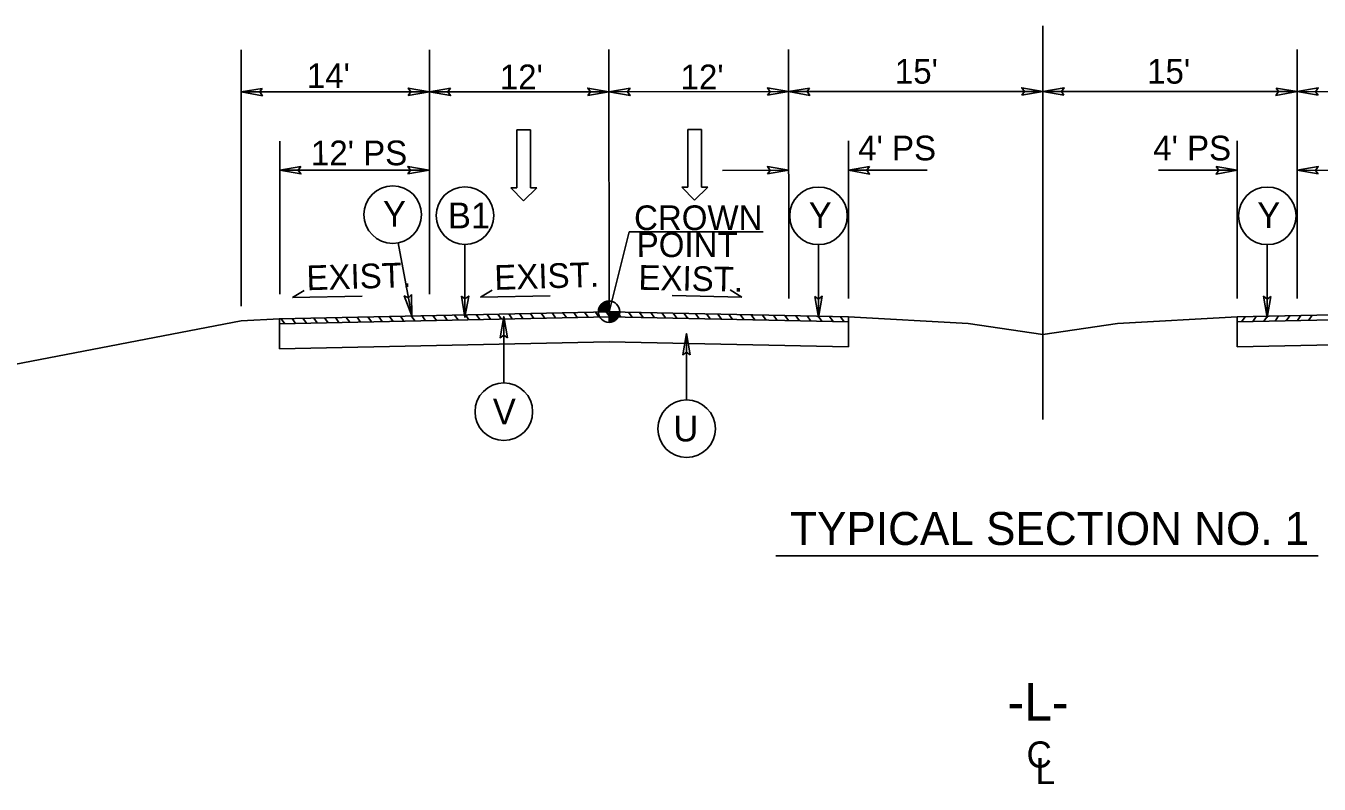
# Model space of a CAD drawing. Extents: x 2241081 to 2251104, y 658534 to 663427.
# Drawn here: x 2248203.4 to 2248635.4, y 662128.3 to 662381.6 of the extents above; entities that cross this region are included whole.
import ezdxf

# ---------------------------------------------------------------- set-up
doc = ezdxf.new("R2010")
doc.units = 0
for name, color, linetype in [('Old_Level_2', 7, 'Continuous'), ('Prop Dimension Text', 7, 'Continuous'), ('Prop Lane Arrow CELL', 7, 'Continuous'), ('Prop Shade Medium', 7, 'Continuous'), ('Prop Terminator CELL', 7, 'Continuous'), ('Typical Arrow Superelevation CELL', 7, 'Continuous'), ('Typical Berm Information CELL', 7, 'Continuous'), ('Typical Grade Point Symbol CELL', 7, 'Continuous'), ('Typical ID Circle CELL', 7, 'Continuous'), ('Typical Terminator CELL', 7, 'Continuous'), ('Typical Text Centerline CELL', 7, 'Continuous'), ('Typical Text Grade Point CELL', 7, 'Continuous'), ('Typical Text ID Circle CELL', 7, 'Continuous'), ('Typical Text Label CELL', 7, 'Continuous')]:
    doc.layers.add(name, color=color, linetype=linetype)

msp = doc.modelspace()

# ---------------------------------------------------------------- linework, layer by layer
at = {"layer": 'Old_Level_2'}
for p, q in [((2248398.2, 662286.1), (2248288.07, 662283.74)), ((2248347.73, 662283.34), (2248346.56, 662284.99)), ((2248351.35, 662283.42), (2248350.18, 662285.07)), ((2248354.97, 662283.5), (2248353.8, 662285.15)), ((2248358.59, 662283.58), (2248357.42, 662285.23)), ((2248362.21, 662283.65), (2248361.04, 662285.3)), ((2248365.83, 662283.73), (2248364.66, 662285.38)), ((2248369.44, 662283.81), (2248368.28, 662285.46)), ((2248373.06, 662283.89), (2248371.9, 662285.54)), ((2248376.68, 662283.96), (2248375.52, 662285.61)), ((2248380.3, 662284.04), (2248379.14, 662285.69)), ((2248383.92, 662284.12), (2248382.76, 662285.77)), ((2248387.54, 662284.2), (2248386.37, 662285.85)), ((2248391.16, 662284.27), (2248389.99, 662285.92)), ((2248394.78, 662284.35), (2248393.61, 662286)), ((2248398.4, 662284.42), (2248397.23, 662286.08)), ((2248398.2, 662286.1), (2248478.2, 662284.39)), ((2248402.13, 662284.34), (2248400.93, 662286.04)), ((2248405.86, 662284.26), (2248404.66, 662285.96)), ((2248409.59, 662284.18), (2248408.39, 662285.88)), ((2248413.33, 662284.1), (2248412.12, 662285.8)), ((2248417.06, 662284.02), (2248415.85, 662285.72)), ((2248420.79, 662283.94), (2248419.58, 662285.64)), ((2248424.52, 662283.86), (2248423.31, 662285.56)), ((2248428.25, 662283.78), (2248427.04, 662285.48)), ((2248431.98, 662283.7), (2248430.77, 662285.4)), ((2248435.71, 662283.62), (2248434.51, 662285.32)), ((2248439.44, 662283.54), (2248438.24, 662285.24)), ((2248443.17, 662283.46), (2248441.97, 662285.16)), ((2248446.9, 662283.38), (2248445.7, 662285.08)), ((2248450.63, 662283.3), (2248449.43, 662285)), ((2248688.02, 662286.1), (2248608.02, 662284.39)), ((2248275.34, 662283.04), (2248166.51, 662262.1)), ((2248288.07, 662283.74), (2248275.34, 662283.04)), ((2248288.07, 662283.74), (2248288.07, 662273.74)), ((2248289.82, 662282.1), (2248288.66, 662283.75)), ((2248293.44, 662282.18), (2248292.28, 662283.83)), ((2248297.06, 662282.26), (2248295.9, 662283.91)), ((2248300.68, 662282.34), (2248299.52, 662283.99)), ((2248304.3, 662282.41), (2248303.13, 662284.06)), ((2248307.92, 662282.49), (2248306.75, 662284.14)), ((2248311.54, 662282.57), (2248310.37, 662284.22)), ((2248315.16, 662282.65), (2248313.99, 662284.3)), ((2248318.78, 662282.72), (2248317.61, 662284.37)), ((2248322.4, 662282.8), (2248321.23, 662284.45)), ((2248326.02, 662282.88), (2248324.85, 662284.53)), ((2248329.63, 662282.96), (2248328.47, 662284.61)), ((2248333.25, 662283.03), (2248332.09, 662284.68)), ((2248336.87, 662283.11), (2248335.71, 662284.76)), ((2248340.49, 662283.19), (2248339.33, 662284.84)), ((2248344.11, 662283.27), (2248342.95, 662284.92)), ((2248454.36, 662283.22), (2248453.16, 662284.92)), ((2248458.09, 662283.14), (2248456.89, 662284.84)), ((2248461.82, 662283.06), (2248460.62, 662284.76)), ((2248465.55, 662282.98), (2248464.35, 662284.68)), ((2248469.28, 662282.9), (2248468.08, 662284.6)), ((2248473.01, 662282.82), (2248471.81, 662284.52)), ((2248476.74, 662282.74), (2248475.54, 662284.44)), ((2248478.2, 662284.39), (2248518.2, 662282.19)), ((2248478.2, 662284.39), (2248478.2, 662274.38)), ((2248518.2, 662282.19), (2248543.11, 662278.53)), ((2248568.02, 662282.19), (2248543.11, 662278.53)), ((2248608.02, 662284.39), (2248568.02, 662282.19)), ((2248608.02, 662284.39), (2248608.02, 662274.38)), ((2248609.48, 662282.74), (2248610.68, 662284.44)), ((2248613.21, 662282.82), (2248614.41, 662284.52)), ((2248616.94, 662282.9), (2248618.14, 662284.6)), ((2248620.67, 662282.98), (2248621.88, 662284.68)), ((2248624.4, 662283.06), (2248625.61, 662284.76)), ((2248628.13, 662283.14), (2248629.34, 662284.84)), ((2248631.86, 662283.22), (2248633.07, 662284.92)), ((2248398.21, 662276.1), (2248288.07, 662273.74)), ((2248398.21, 662276.1), (2248478.2, 662274.38)), ((2248688.02, 662276.1), (2248608.02, 662274.38))]:
    msp.add_line(p, q, dxfattribs=at)
at = {"layer": 'Prop Dimension Text'}
for p, q in [((2248275.34, 662287.93), (2248275.29, 662373.52)), ((2248338.2, 662291.97), (2248338.15, 662373.59)), ((2248398.15, 662366.85), (2248398.15, 662373.63)), ((2248398.2, 662286.1), (2248398.15, 662372.95)), ((2248458.2, 662290.48), (2248458.15, 662373.67)), ((2248628.02, 662290.48), (2248628.07, 662373.67)), ((2248338.16, 662359.52), (2248275.3, 662359.49)), ((2248398.16, 662359.56), (2248338.16, 662359.52)), ((2248458.16, 662359.6), (2248398.16, 662359.56)), ((2248543.13, 662359.65), (2248458.16, 662359.6)), ((2248543.13, 662359.65), (2248628.06, 662359.6)), ((2248628.06, 662359.6), (2248688.06, 662359.56)), ((2248288.2, 662291.94), (2248288.17, 662343.05)), ((2248478.2, 662290.48), (2248478.17, 662343.17)), ((2248608.02, 662290.48), (2248608.05, 662343.17)), ((2248338.05, 662333.39), (2248288.17, 662333.36)), ((2248436.11, 662333.31), (2248458.17, 662333.33)), ((2248478.17, 662333.34), (2248504.51, 662333.35)), ((2248608.05, 662333.34), (2248581.72, 662333.35)), ((2248650.11, 662333.31), (2248628.05, 662333.33))]:
    msp.add_line(p, q, dxfattribs=at)
at = {"layer": 'Prop Lane Arrow CELL'}
for p, q in [((2248367.43, 662346.82), (2248367.41, 662327.52)), ((2248371.97, 662346.82), (2248367.43, 662346.82)), ((2248371.96, 662327.52), (2248371.97, 662346.82)), ((2248424.55, 662346.96), (2248424.53, 662327.66)), ((2248429.09, 662346.96), (2248424.55, 662346.96)), ((2248429.08, 662327.66), (2248429.09, 662346.96)), ((2248367.41, 662327.52), (2248365.35, 662327.52)), ((2248365.35, 662327.52), (2248369.62, 662323.18)), ((2248369.62, 662323.18), (2248374.03, 662327.52)), ((2248374.03, 662327.52), (2248371.96, 662327.52)), ((2248424.53, 662327.66), (2248422.47, 662327.67)), ((2248422.47, 662327.67), (2248426.74, 662323.32)), ((2248426.74, 662323.32), (2248431.15, 662327.66)), ((2248431.15, 662327.66), (2248429.08, 662327.66))]:
    msp.add_line(p, q, dxfattribs=at)
at = {"layer": 'Prop Shade Medium'}
for points in [[(2248478.2, 662284.39), (2248398.2, 662286.1), (2248288.07, 662283.74), (2248288.07, 662282.07), (2248398.2, 662284.42), (2248478.2, 662282.71)], [(2248608.02, 662284.39), (2248688.02, 662286.1), (2248748.02, 662284.81), (2248798.15, 662283.74), (2248798.15, 662282.07), (2248688.02, 662284.42), (2248608.02, 662282.71)]]:
    msp.add_lwpolyline(points, close=True, dxfattribs=at)
at = {"layer": 'Prop Terminator CELL'}
msp.add_lwpolyline([(2248332.21, 662291.81), (2248332.33, 662284.69), (2248329.79, 662291.39), (2248331.19, 662290.74)], close=True, dxfattribs=at)
at = {"layer": 'Typical Arrow Superelevation CELL'}
for p, q in [((2248292.44, 662290.85), (2248296.36, 662293.21)), ((2248292.44, 662290.85), (2248315.75, 662291.31)), ((2248355.2, 662290.97), (2248359.11, 662293.34)), ((2248355.2, 662290.97), (2248378.5, 662291.43)), ((2248442.6, 662291.01), (2248419.29, 662291.48)), ((2248442.6, 662291.01), (2248438.68, 662293.38))]:
    msp.add_line(p, q, dxfattribs=at)
at = {"layer": 'Typical Grade Point Symbol CELL'}
for p, q in [((2248398.2, 662286.1), (2248404.93, 662312.73)), ((2248398.19, 662289.68), (2248398.2, 662286.1)), ((2248398.2, 662286.1), (2248398.19, 662289.68)), ((2248394.62, 662286.1), (2248398.2, 662286.1)), ((2248401.78, 662286.1), (2248398.2, 662286.1)), ((2248398.2, 662286.1), (2248398.2, 662282.52))]:
    msp.add_line(p, q, dxfattribs=at)
for points in [[(2248396.5, 662286.1), (2248396.5, 662289.25)], [(2248396.57, 662286.1), (2248396.57, 662289.29)], [(2248396.64, 662286.1), (2248396.64, 662289.32)], [(2248396.71, 662286.1), (2248396.71, 662289.35)], [(2248396.79, 662286.1), (2248396.79, 662289.38)], [(2248396.86, 662286.1), (2248396.86, 662289.42)], [(2248396.93, 662286.1), (2248396.93, 662289.45)], [(2248397, 662286.1), (2248397, 662289.47)], [(2248397.07, 662286.1), (2248397.07, 662289.5)], [(2248397.14, 662286.1), (2248397.14, 662289.52)], [(2248397.21, 662286.1), (2248397.21, 662289.54)], [(2248397.29, 662286.1), (2248397.29, 662289.56)], [(2248397.36, 662286.1), (2248397.36, 662289.58)], [(2248397.43, 662286.1), (2248397.43, 662289.59)], [(2248397.5, 662286.1), (2248397.5, 662289.61)], [(2248397.57, 662286.1), (2248397.57, 662289.62)], [(2248397.64, 662286.1), (2248397.64, 662289.63)], [(2248397.72, 662286.1), (2248397.72, 662289.65)], [(2248397.79, 662286.1), (2248397.79, 662289.66)], [(2248397.86, 662286.1), (2248397.86, 662289.66)], [(2248397.93, 662286.1), (2248397.93, 662289.67)], [(2248398, 662286.1), (2248398, 662289.67)], [(2248398.07, 662286.1), (2248398.07, 662289.68)], [(2248398.15, 662286.1), (2248398.15, 662289.68), (2248398.15, 662289.68)], [(2248394.64, 662286.1), (2248394.64, 662286.49)], [(2248394.71, 662286.1), (2248394.71, 662286.91)], [(2248394.78, 662286.1), (2248394.78, 662287.16)], [(2248394.85, 662286.1), (2248394.85, 662287.38)], [(2248394.92, 662286.1), (2248394.92, 662287.55)], [(2248394.99, 662286.1), (2248394.99, 662287.7)], [(2248395.07, 662286.1), (2248395.07, 662287.83)], [(2248395.14, 662286.1), (2248395.14, 662287.96)], [(2248395.21, 662286.1), (2248395.21, 662288.07)], [(2248395.28, 662286.1), (2248395.28, 662288.18)], [(2248395.35, 662286.1), (2248395.35, 662288.27)], [(2248395.42, 662286.1), (2248395.42, 662288.36)], [(2248395.5, 662286.1), (2248395.5, 662288.45)], [(2248395.57, 662286.1), (2248395.57, 662288.53)], [(2248395.64, 662286.1), (2248395.64, 662288.6)], [(2248395.71, 662286.1), (2248395.71, 662288.68)], [(2248395.78, 662286.1), (2248395.78, 662288.74)], [(2248395.85, 662286.1), (2248395.85, 662288.8)], [(2248395.93, 662286.1), (2248395.93, 662288.87)], [(2248396, 662286.1), (2248396, 662288.92)], [(2248396.07, 662286.1), (2248396.07, 662288.98)], [(2248396.14, 662286.1), (2248396.14, 662289.03)], [(2248396.21, 662286.1), (2248396.21, 662289.07)], [(2248396.28, 662286.1), (2248396.28, 662289.12)], [(2248396.36, 662286.1), (2248396.36, 662289.17)], [(2248396.43, 662286.1), (2248396.43, 662289.21)], [(2248398.23, 662282.52), (2248398.23, 662282.52), (2248398.23, 662286.1)], [(2248398.3, 662282.52), (2248398.3, 662286.1)], [(2248398.38, 662282.53), (2248398.38, 662286.1)], [(2248398.45, 662282.53), (2248398.45, 662286.1)], [(2248398.52, 662282.53), (2248398.52, 662286.1)], [(2248398.59, 662282.54), (2248398.59, 662286.1)], [(2248398.66, 662282.55), (2248398.66, 662286.1)], [(2248398.73, 662282.56), (2248398.73, 662286.1)], [(2248398.81, 662282.57), (2248398.81, 662286.1)], [(2248398.88, 662282.58), (2248398.88, 662286.1)], [(2248398.95, 662282.6), (2248398.95, 662286.1)], [(2248399.02, 662282.61), (2248399.02, 662286.1)], [(2248399.09, 662282.63), (2248399.09, 662286.1)], [(2248399.16, 662282.65), (2248399.16, 662286.1)], [(2248399.24, 662282.67), (2248399.24, 662286.1)], [(2248399.31, 662282.69), (2248399.31, 662286.1)], [(2248399.38, 662282.72), (2248399.38, 662286.1)], [(2248399.45, 662282.74), (2248399.45, 662286.1)], [(2248399.52, 662282.77), (2248399.52, 662286.1)], [(2248399.59, 662282.8), (2248399.59, 662286.1)], [(2248399.67, 662282.84), (2248399.67, 662286.1)], [(2248399.74, 662282.87), (2248399.74, 662286.1)], [(2248399.81, 662282.9), (2248399.81, 662286.1)], [(2248399.88, 662282.94), (2248399.88, 662286.1)], [(2248399.95, 662282.98), (2248399.95, 662286.1)], [(2248400.02, 662283.02), (2248400.02, 662286.1)], [(2248400.09, 662283.06), (2248400.09, 662286.1)], [(2248400.17, 662283.11), (2248400.17, 662286.1)], [(2248400.24, 662283.15), (2248400.24, 662286.1)], [(2248400.31, 662283.21), (2248400.31, 662286.1)], [(2248400.38, 662283.26), (2248400.38, 662286.1)], [(2248400.45, 662283.31), (2248400.45, 662286.1)], [(2248400.52, 662283.38), (2248400.52, 662286.1)], [(2248400.6, 662283.44), (2248400.6, 662286.1)], [(2248400.67, 662283.5), (2248400.67, 662286.1)], [(2248400.74, 662283.58), (2248400.74, 662286.1)], [(2248400.81, 662283.65), (2248400.81, 662286.1)], [(2248400.88, 662283.73), (2248400.88, 662286.1)], [(2248400.95, 662283.81), (2248400.95, 662286.1)], [(2248401.03, 662283.9), (2248401.03, 662286.1)], [(2248401.1, 662284), (2248401.1, 662286.1)], [(2248401.17, 662284.1), (2248401.17, 662286.1)], [(2248401.24, 662284.21), (2248401.24, 662286.1)], [(2248401.31, 662284.33), (2248401.31, 662286.1)], [(2248401.38, 662284.46), (2248401.38, 662286.1)], [(2248401.46, 662284.61), (2248401.46, 662286.1)], [(2248401.53, 662284.78), (2248401.53, 662286.1)], [(2248401.6, 662284.98), (2248401.6, 662286.1)], [(2248401.67, 662285.22), (2248401.67, 662286.1)], [(2248401.74, 662285.59), (2248401.74, 662286.1)]]:
    msp.add_lwpolyline(points, dxfattribs=at)
msp.add_circle((2248398.2, 662286.1), 3.58, dxfattribs=at)
for start, end in [(90.0094, 180.0094), (270.0094, 0.0094)]:
    msp.add_arc((2248398.2, 662286.1), 3.58, start, end, dxfattribs=at)
at = {"layer": 'Typical ID Circle CELL'}
for p, q in [((2248327.71, 662309.1), (2248332.33, 662284.69)), ((2248350.06, 662308.61), (2248350.06, 662284.28)), ((2248468.16, 662308.51), (2248468.16, 662284.18)), ((2248618.1, 662308.51), (2248618.1, 662284.18)), ((2248363.03, 662262.31), (2248363.03, 662284.46)), ((2248424.08, 662256.65), (2248424.08, 662278.79))]:
    msp.add_line(p, q, dxfattribs=at)
for centre in [(2248325.92, 662318.55), (2248350.06, 662318.22), (2248468.16, 662318.12), (2248618.1, 662318.12), (2248363.03, 662252.7), (2248424.08, 662247.03)]:
    msp.add_circle(centre, 9.62, dxfattribs=at)
at = {"layer": 'Typical Terminator CELL'}
for points in [[(2248282.33, 662360.7), (2248275.3, 662359.49), (2248282.37, 662358.24), (2248281.47, 662359.49)], [(2248331.13, 662358.31), (2248338.16, 662359.52), (2248331.09, 662360.77), (2248331.99, 662359.52)], [(2248345.19, 662360.74), (2248338.16, 662359.52), (2248345.23, 662358.28), (2248344.33, 662359.53)], [(2248391.13, 662358.34), (2248398.16, 662359.56), (2248391.09, 662360.81), (2248391.99, 662359.56)], [(2248405.19, 662360.77), (2248398.16, 662359.56), (2248405.23, 662358.31), (2248404.33, 662359.56)], [(2248451.13, 662358.38), (2248458.16, 662359.6), (2248451.09, 662360.84), (2248451.99, 662359.59)], [(2248465.19, 662360.81), (2248458.16, 662359.6), (2248465.23, 662358.35), (2248464.33, 662359.6)], [(2248536.1, 662358.43), (2248543.13, 662359.65), (2248536.06, 662360.89), (2248536.96, 662359.64)], [(2248550.16, 662358.43), (2248543.13, 662359.65), (2248550.2, 662360.89), (2248549.3, 662359.64)], [(2248621.04, 662360.81), (2248628.06, 662359.6), (2248620.99, 662358.35), (2248621.89, 662359.6)], [(2248635.09, 662358.38), (2248628.06, 662359.6), (2248635.13, 662360.84), (2248634.24, 662359.59)], [(2248295.2, 662334.58), (2248288.17, 662333.36), (2248295.24, 662332.12), (2248294.35, 662333.37)], [(2248331.02, 662332.18), (2248338.05, 662333.39), (2248330.98, 662334.64), (2248331.88, 662333.39)], [(2248451.15, 662332.11), (2248458.17, 662333.33), (2248451.1, 662334.57), (2248452, 662333.32)], [(2248485.2, 662334.55), (2248478.17, 662333.34), (2248485.24, 662332.09), (2248484.35, 662333.34)], [(2248601.02, 662334.55), (2248608.05, 662333.34), (2248600.98, 662332.09), (2248601.88, 662333.34)], [(2248635.08, 662332.11), (2248628.05, 662333.33), (2248635.12, 662334.57), (2248634.22, 662333.32)], [(2248348.85, 662291.31), (2248350.06, 662284.28), (2248351.31, 662291.35), (2248350.06, 662290.45)], [(2248466.95, 662291.21), (2248468.16, 662284.18), (2248469.41, 662291.25), (2248468.16, 662290.35)], [(2248619.31, 662291.21), (2248618.1, 662284.18), (2248616.85, 662291.25), (2248618.1, 662290.35)], [(2248364.24, 662277.43), (2248363.03, 662284.46), (2248361.78, 662277.39), (2248363.03, 662278.28)], [(2248425.29, 662271.76), (2248424.08, 662278.79), (2248422.83, 662271.72), (2248424.08, 662272.62)]]:
    msp.add_lwpolyline(points, close=True, dxfattribs=at)
at = {"layer": 'Typical Text Centerline CELL'}
msp.add_line((2248543.13, 662250.11), (2248543.13, 662381.57), dxfattribs=at)
at = {"layer": 'Typical Text Grade Point CELL'}
msp.add_line((2248404.93, 662312.73), (2248449.73, 662312.76), dxfattribs=at)
at = {"layer": 'Typical Text Label CELL'}
msp.add_line((2248453.9, 662204.53), (2248635.08, 662204.53), dxfattribs=at)

# ---------------------------------------------------------------- texts
at = {"layer": 'Prop Dimension Text'}
for s, height, rotation, p in [("14'", 8.25, 0.0349, (2248297.23, 662360.79)), ("12'", 8.25, 0.0349, (2248361.7, 662360.39)), ("12'", 8.25, 0.0349, (2248422.09, 662360.39)), ("15'", 8.25, 0.0349, (2248493.68, 662362.27)), ("15'", 8.25, 359.965, (2248577.95, 662362.28)), ("12' PS", 8.25, 0.0349, (2248298.6, 662335)), ("4' PS", 8.25, 0.0349, (2248481.42, 662336.64)), ("4' PS", 8.25, 359.965, (2248579.98, 662336.66)), ('-L-', 12.5, 0.0349, (2248531.28, 662149.57))]:
    msp.add_text(s, height=height, rotation=rotation, dxfattribs=at).set_placement(p)
at = {"layer": 'Typical Berm Information CELL'}
for rotation, p in [(1.8083, (2248297.24, 662293.25)), (1.8083, (2248360, 662293.37)), (358.854, (2248407.95, 662293.45))]:
    msp.add_text('EXIST.', height=8.25, rotation=rotation, dxfattribs=at).set_placement(p)
at = {"layer": 'Typical Text Centerline CELL'}
for s, rotation, p in [('C', 0.0349, (2248537.66, 662133.84)), ('L', 359.9818, (2248540.69, 662128.34))]:
    msp.add_text(s, height=8.76, rotation=rotation, dxfattribs=at).set_placement(p)
at = {"layer": 'Typical Text Grade Point CELL'}
for s, p in [('CROWN', (2248406.55, 662313.35)), ('POINT', (2248407.43, 662304.35))]:
    msp.add_text(s, height=8.25, rotation=0.0349, dxfattribs=at).set_placement(p)
at = {"layer": 'Typical Text ID Circle CELL'}
for s, height, p in [('Y', 8.61, (2248322.66, 662314.47)), ('B1', 8.608, (2248344.37, 662313.95)), ('Y', 8.61, (2248464.9, 662314.05)), ('Y', 8.61, (2248614.74, 662314.05)), ('V', 8.61, (2248359.36, 662248.46)), ('U', 8.61, (2248419.7, 662242.79))]:
    msp.add_text(s, height=height, rotation=359.9999, dxfattribs=at).set_placement(p)
at = {"layer": 'Typical Text Label CELL'}
msp.add_text('TYPICAL SECTION NO. 1', height=11.0106, dxfattribs=at).set_placement((2248458.68, 662208.21))

doc.saveas('drawing.dxf')
